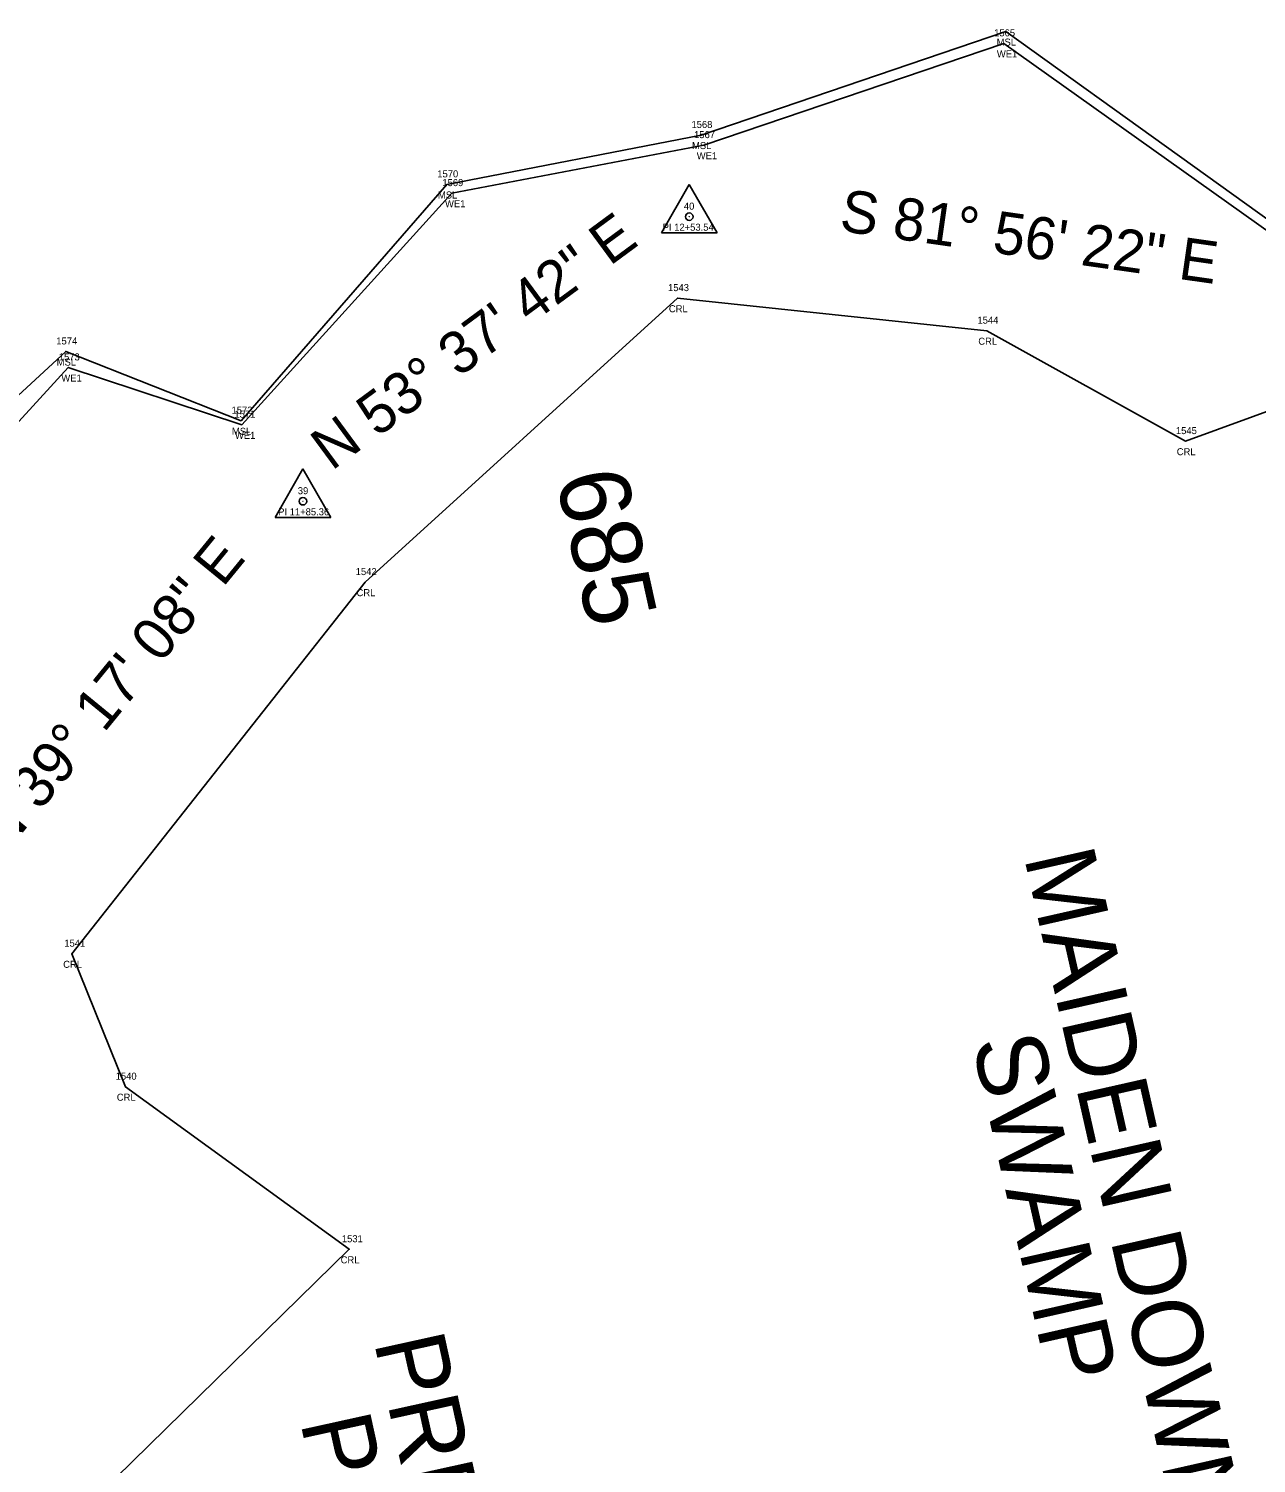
# Model space of a CAD drawing. Extents: x 2521558 to 2525396, y 882711 to 887632.
# Drawn here: x 2523844.7 to 2524019.1, y 885124.5 to 885328.4 of the extents above; entities that cross this region are included whole.
import ezdxf

# ---------------------------------------------------------------- set-up
doc = ezdxf.new("R2010")
doc.units = 0
for name, color, linetype in [('RD_EX_H2O', 7, 'Continuous'), ('RD_EX_H2O_txCode', 7, 'Continuous'), ('RD_EX_Misc', 7, 'Continuous'), ('RD_EX_Misc_txCode', 7, 'Continuous'), ('RD_EX_RW_TX', 7, 'Continuous'), ('RD_HC_Cl', 7, 'Continuous'), ('RD_HC_Data', 7, 'Continuous'), ('RD_HC_TX_Sta50', 7, 'Continuous'), ('RD_HC_txCode', 7, 'Continuous'), ('RD_SMD_Locator', 7, 'Continuous')]:
    doc.layers.add(name, color=color, linetype=linetype)

msp = doc.modelspace()

# ---------------------------------------------------------------- linework, layer by layer
at = {"layer": 'RD_EX_H2O'}
for points in [[(2523845.24, 885110.83), (2523890.25, 885154.93), (2523858.43, 885178.04), (2523850.81, 885196.93), (2523892.51, 885249.74), (2523936.89, 885290.09), (2523980.86, 885285.47), (2524009.06, 885269.77), (2524037.39, 885280.09), (2524039.52, 885283.17), (2524058.23, 885288.29), (2524091.23, 885302.32), (2524154.23, 885321.67), (2524199.79, 885382.59)], [(2524064.86, 885165.15), (2524036.37, 885213.78), (2524057.22, 885252.72), (2524031.95, 885291.63), (2523983.25, 885326.3), (2523940.61, 885311.83), (2523904.84, 885305.01), (2523874.98, 885272.1), (2523850.32, 885280.24), (2523830.66, 885258.8), (2523826.93, 885206.61)]]:
    msp.add_lwpolyline(points, dxfattribs=at)
at = {"layer": 'RD_EX_Misc'}
msp.add_lwpolyline([(2524066.31, 885165.35), (2524037.3, 885214.15), (2524057.95, 885253.07), (2524039.52, 885283.17), (2524032.92, 885292.57), (2523983.53, 885327.98), (2523940.24, 885313.27), (2523904.13, 885306.25), (2523874.86, 885272.67), (2523849.96, 885282.51), (2523827.65, 885261.93), (2523821.38, 885209.28)], dxfattribs=at)
at = {"layer": 'RD_HC_Data'}
for p, q in [((2523934.59, 885299.37), (2523938.56, 885306.25)), ((2523938.56, 885306.25), (2523942.53, 885299.37)), ((2523934.59, 885299.37), (2523942.53, 885299.37)), ((2523879.69, 885258.94), (2523883.66, 885265.82)), ((2523883.66, 885265.82), (2523887.63, 885258.94)), ((2523879.69, 885258.94), (2523887.63, 885258.94))]:
    msp.add_line(p, q, dxfattribs=at)
for centre in [(2523938.56, 885301.67), (2523883.66, 885261.23)]:
    msp.add_circle(centre, 0.529, dxfattribs=at)
at = {"layer": 'RD_SMD_Locator'}
for centre in [(2523983.25, 885326.3), (2523983.53, 885327.98), (2523940.24, 885313.27), (2523940.61, 885311.83), (2523904.13, 885306.25), (2523904.84, 885305.01), (2523938.56, 885301.67), (2523936.89, 885290.09), (2523980.86, 885285.47), (2523849.96, 885282.51), (2523850.32, 885280.24), (2523874.86, 885272.67), (2523874.98, 885272.1), (2524009.06, 885269.77), (2523883.66, 885261.23), (2523892.51, 885249.74), (2523850.81, 885196.93), (2523858.43, 885178.04), (2523890.25, 885154.93)]:
    msp.add_circle(centre, 0.001, dxfattribs=at)

# ---------------------------------------------------------------- texts
at = {"layer": 'RD_EX_H2O_txCode'}
for s, p in [('1565', (2523981.88, 885327.3)), ('WE1', (2523982.27, 885324.3)), ('1567', (2523939.24, 885312.83)), ('WE1', (2523939.62, 885309.83)), ('1569', (2523903.47, 885306.01)), ('WE1', (2523903.85, 885303.01)), ('1543', (2523935.54, 885291.09)), ('CRL', (2523935.66, 885288.09)), ('1544', (2523979.51, 885286.47)), ('CRL', (2523979.63, 885283.47)), ('1573', (2523848.97, 885281.24)), ('WE1', (2523849.33, 885278.24)), ('1571', (2523873.92, 885273.1)), ('1545', (2524007.71, 885270.77)), ('WE1', (2523874, 885270.1)), ('CRL', (2524007.83, 885267.77)), ('1542', (2523891.16, 885250.74)), ('CRL', (2523891.28, 885247.74)), ('1541', (2523849.75, 885197.93)), ('CRL', (2523849.59, 885194.93)), ('1540', (2523857.05, 885179.04)), ('CRL', (2523857.21, 885176.04)), ('1531', (2523889.19, 885155.93)), ('CRL', (2523889.02, 885152.93))]:
    msp.add_text(s, height=1, dxfattribs=at).set_placement(p)
at = {"layer": 'RD_EX_Misc_txCode'}
for s, p in [('MSL', (2523982.24, 885325.98)), ('1568', (2523938.87, 885314.27)), ('MSL', (2523938.95, 885311.27)), ('1570', (2523902.75, 885307.25)), ('MSL', (2523902.84, 885304.25)), ('1574', (2523848.61, 885283.51)), ('MSL', (2523848.67, 885280.51)), ('1572', (2523873.51, 885273.67)), ('MSL', (2523873.57, 885270.67))]:
    msp.add_text(s, height=1, dxfattribs=at).set_placement(p)
at = {"layer": 'RD_EX_RW_TX'}
for s, p in [("PRES. 75' R/W ", (2523893.73, 885141.81)), ('PROJ. 386-C ', (2523883.26, 885130.4))]:
    msp.add_text(s, height=10, rotation=282.4185, dxfattribs=at).set_placement(p)
at = {"layer": 'RD_HC_Cl'}
for s, p in [('MAIDEN DOWN ', (2523986.11, 885210.68)), ('SWAMP', (2523978.69, 885184.44))]:
    msp.add_text(s, height=10, rotation=282.7283, dxfattribs=at).set_placement(p)
at = {"layer": 'RD_HC_Data'}
for s, rotation, p in [('S 81%%d 56\' 22" E', 351.9395, (2523959.76, 885299.67)), ('N 53%%d 37\' 42" E', 36.3717, (2523887.74, 885265.48)), ('N 39%%d 17\' 08" E', 50.7144, (2523841.2, 885210.9))]:
    msp.add_text(s, height=6, rotation=rotation, dxfattribs=at).set_placement(p)
at = {"layer": 'RD_HC_TX_Sta50'}
msp.add_text('685', height=10, rotation=282.4185, dxfattribs=at).set_placement((2523919.56, 885264.64))
at = {"layer": 'RD_HC_txCode'}
for s, p in [('40', (2523937.79, 885302.67)), ('PI 12+53.54', (2523934.78, 885299.67)), ('39', (2523882.93, 885262.23)), ('PI 11+85.36', (2523880.14, 885259.23))]:
    msp.add_text(s, height=1, dxfattribs=at).set_placement(p)

doc.saveas('drawing.dxf')
